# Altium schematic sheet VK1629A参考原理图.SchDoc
size A3
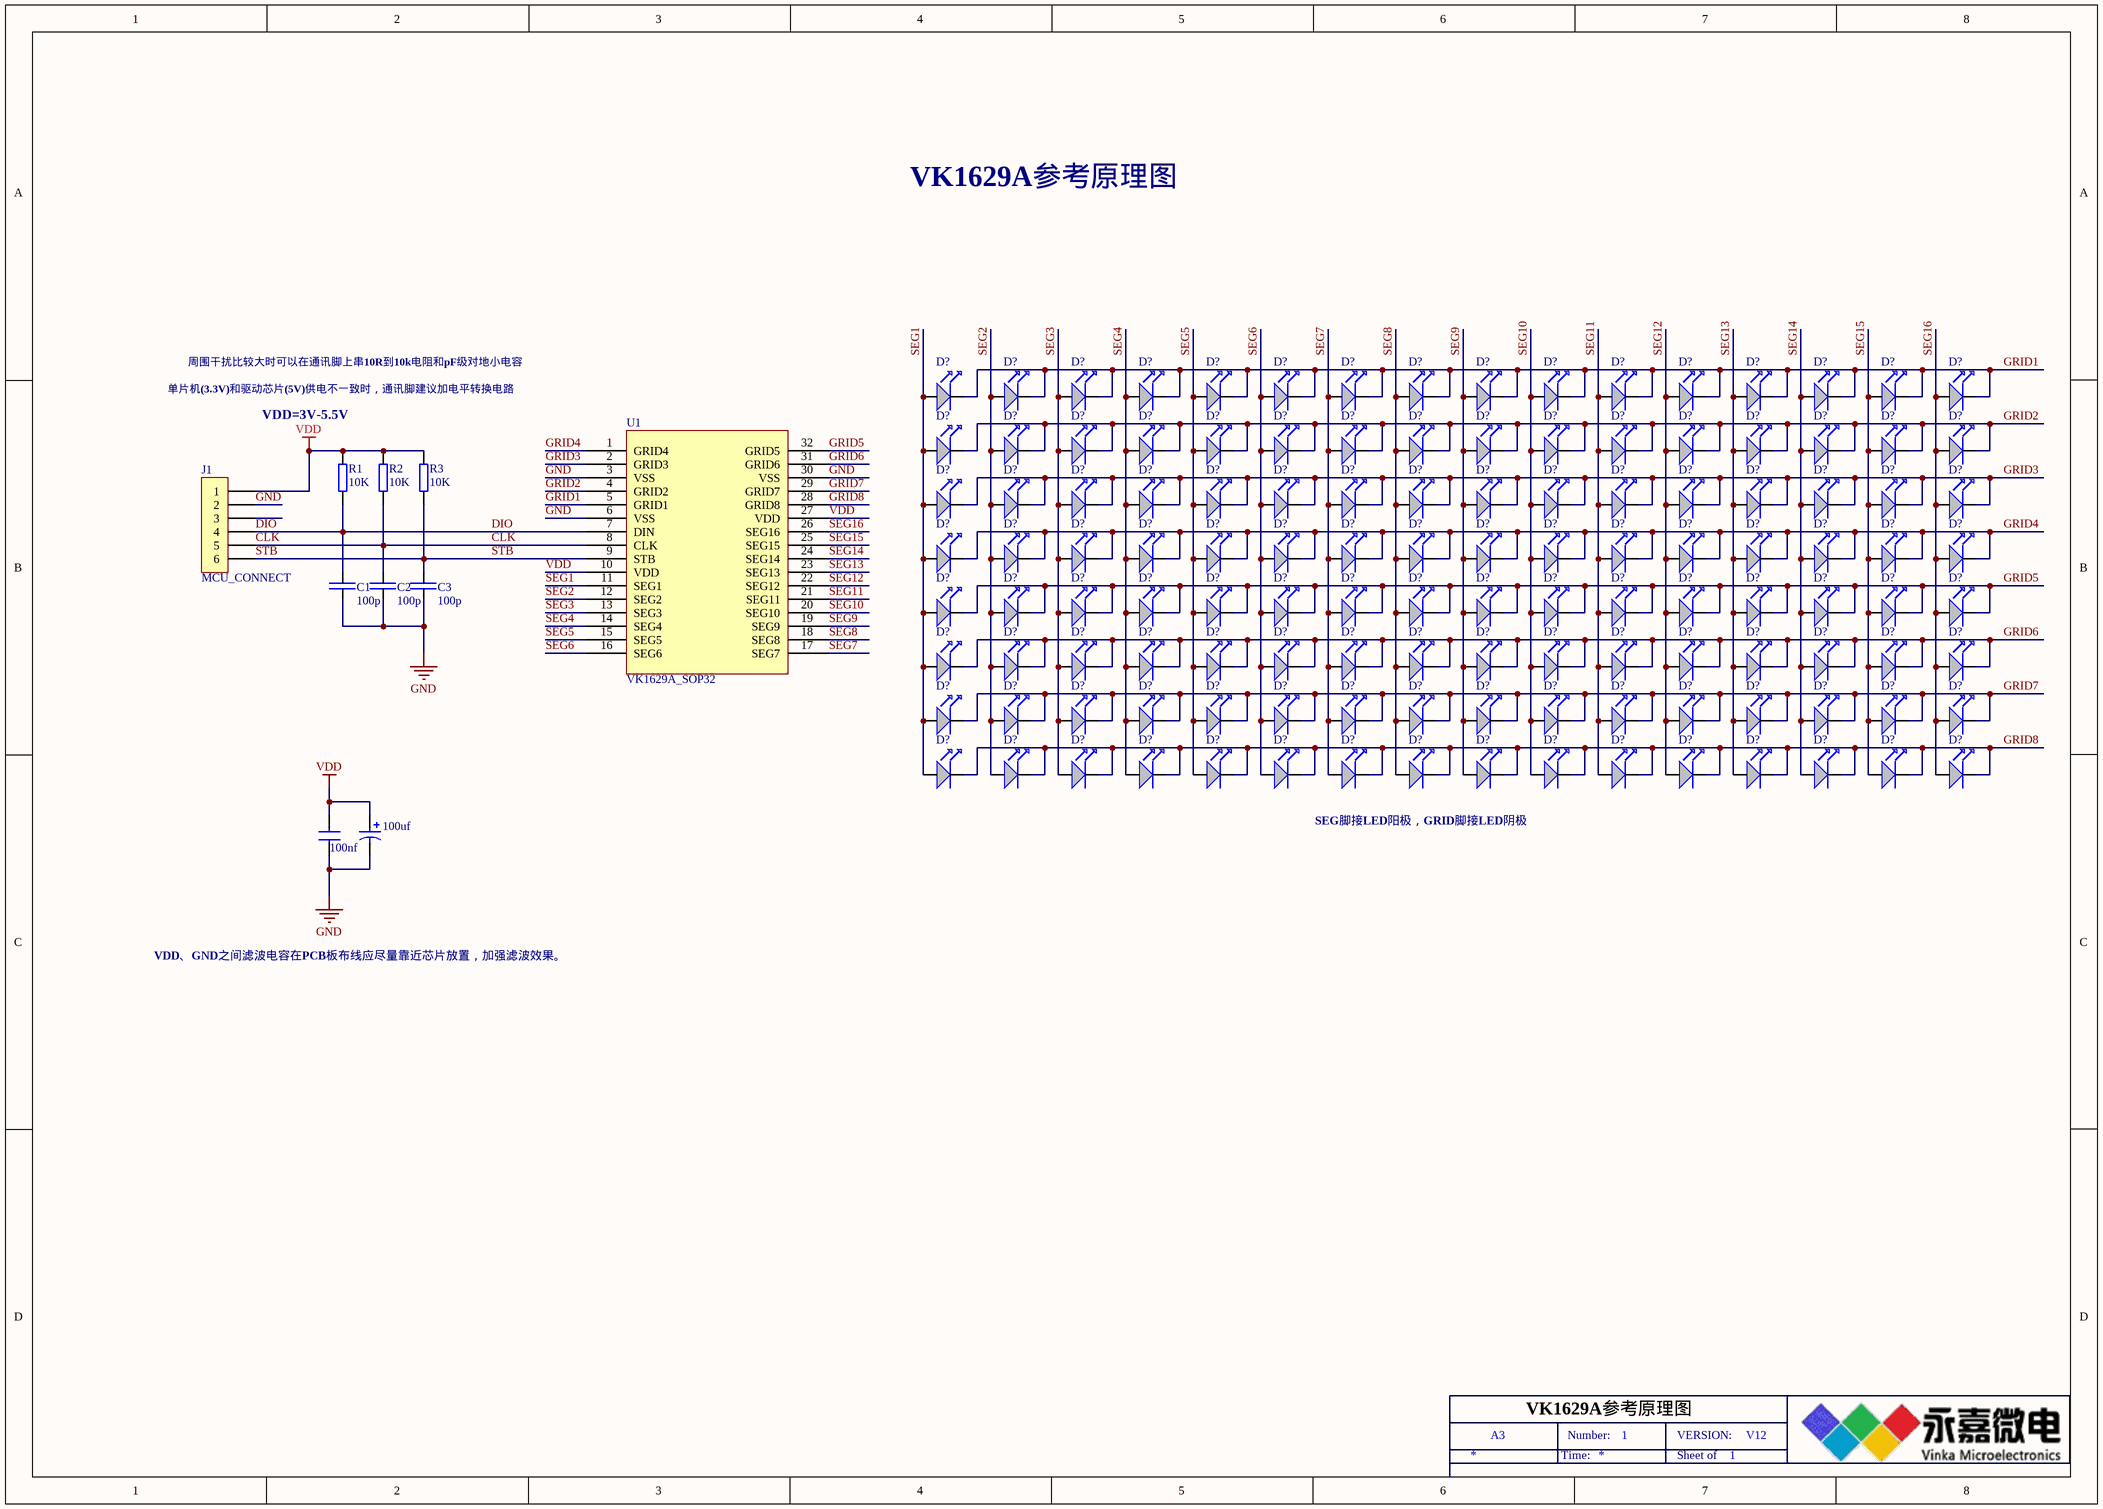
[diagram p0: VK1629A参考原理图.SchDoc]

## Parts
(Parts that share a designator on the sheet are numbered #1, #2 ... from top to bottom, then left to right.)
100nf  CAP  (value not drawn)
100uf  CAP2  (value not drawn)
C1  100p  [C0603]
C2  100p  [C0603]
C3  100p  [C0603]
D?#1  (no value)  [1206-LED]
D?#2  (no value)  [1206-LED]
D?#3  (no value)  [1206-LED]
D?#4  (no value)  [1206-LED]
D?#5  (no value)  [1206-LED]
D?#6  (no value)  [1206-LED]
D?#7  (no value)  [1206-LED]
D?#8  (no value)  [1206-LED]
D?#9  (no value)  [1206-LED]
D?#10  (no value)  [1206-LED]
D?#11  (no value)  [1206-LED]
D?#12  (no value)  [1206-LED]
D?#13  (no value)  [1206-LED]
D?#14  (no value)  [1206-LED]
D?#15  (no value)  [1206-LED]
D?#16  (no value)  [1206-LED]
D?#17  (no value)  [1206-LED]
D?#18  (no value)  [1206-LED]
D?#19  (no value)  [1206-LED]
D?#20  (no value)  [1206-LED]
D?#21  (no value)  [1206-LED]
D?#22  (no value)  [1206-LED]
D?#23  (no value)  [1206-LED]
D?#24  (no value)  [1206-LED]
D?#25  (no value)  [1206-LED]
D?#26  (no value)  [1206-LED]
D?#27  (no value)  [1206-LED]
D?#28  (no value)  [1206-LED]
D?#29  (no value)  [1206-LED]
D?#30  (no value)  [1206-LED]
D?#31  (no value)  [1206-LED]
D?#32  (no value)  [1206-LED]
D?#33  (no value)  [1206-LED]
D?#34  (no value)  [1206-LED]
D?#35  (no value)  [1206-LED]
D?#36  (no value)  [1206-LED]
D?#37  (no value)  [1206-LED]
D?#38  (no value)  [1206-LED]
D?#39  (no value)  [1206-LED]
D?#40  (no value)  [1206-LED]
D?#41  (no value)  [1206-LED]
D?#42  (no value)  [1206-LED]
D?#43  (no value)  [1206-LED]
D?#44  (no value)  [1206-LED]
D?#45  (no value)  [1206-LED]
D?#46  (no value)  [1206-LED]
D?#47  (no value)  [1206-LED]
D?#48  (no value)  [1206-LED]
D?#49  (no value)  [1206-LED]
D?#50  (no value)  [1206-LED]
D?#51  (no value)  [1206-LED]
D?#52  (no value)  [1206-LED]
D?#53  (no value)  [1206-LED]
D?#54  (no value)  [1206-LED]
D?#55  (no value)  [1206-LED]
D?#56  (no value)  [1206-LED]
D?#57  (no value)  [1206-LED]
D?#58  (no value)  [1206-LED]
D?#59  (no value)  [1206-LED]
D?#60  (no value)  [1206-LED]
D?#61  (no value)  [1206-LED]
D?#62  (no value)  [1206-LED]
D?#63  (no value)  [1206-LED]
D?#64  (no value)  [1206-LED]
D?#65  (no value)  [1206-LED]
D?#66  (no value)  [1206-LED]
D?#67  (no value)  [1206-LED]
D?#68  (no value)  [1206-LED]
D?#69  (no value)  [1206-LED]
D?#70  (no value)  [1206-LED]
D?#71  (no value)  [1206-LED]
D?#72  (no value)  [1206-LED]
D?#73  (no value)  [1206-LED]
D?#74  (no value)  [1206-LED]
D?#75  (no value)  [1206-LED]
D?#76  (no value)  [1206-LED]
D?#77  (no value)  [1206-LED]
D?#78  (no value)  [1206-LED]
D?#79  (no value)  [1206-LED]
D?#80  (no value)  [1206-LED]
D?#81  (no value)  [1206-LED]
D?#82  (no value)  [1206-LED]
D?#83  (no value)  [1206-LED]
D?#84  (no value)  [1206-LED]
D?#85  (no value)  [1206-LED]
D?#86  (no value)  [1206-LED]
D?#87  (no value)  [1206-LED]
D?#88  (no value)  [1206-LED]
D?#89  (no value)  [1206-LED]
D?#90  (no value)  [1206-LED]
D?#91  (no value)  [1206-LED]
D?#92  (no value)  [1206-LED]
D?#93  (no value)  [1206-LED]
D?#94  (no value)  [1206-LED]
D?#95  (no value)  [1206-LED]
D?#96  (no value)  [1206-LED]
D?#97  (no value)  [1206-LED]
D?#98  (no value)  [1206-LED]
D?#99  (no value)  [1206-LED]
D?#100  (no value)  [1206-LED]
D?#101  (no value)  [1206-LED]
D?#102  (no value)  [1206-LED]
D?#103  (no value)  [1206-LED]
D?#104  (no value)  [1206-LED]
D?#105  (no value)  [1206-LED]
D?#106  (no value)  [1206-LED]
D?#107  (no value)  [1206-LED]
D?#108  (no value)  [1206-LED]
D?#109  (no value)  [1206-LED]
D?#110  (no value)  [1206-LED]
D?#111  (no value)  [1206-LED]
D?#112  (no value)  [1206-LED]
D?#113  (no value)  [1206-LED]
D?#114  (no value)  [1206-LED]
D?#115  (no value)  [1206-LED]
D?#116  (no value)  [1206-LED]
D?#117  (no value)  [1206-LED]
D?#118  (no value)  [1206-LED]
D?#119  (no value)  [1206-LED]
D?#120  (no value)  [1206-LED]
D?#121  (no value)  [1206-LED]
D?#122  (no value)  [1206-LED]
D?#123  (no value)  [1206-LED]
D?#124  (no value)  [1206-LED]
D?#125  (no value)  [1206-LED]
D?#126  (no value)  [1206-LED]
D?#127  (no value)  [1206-LED]
D?#128  (no value)  [1206-LED]
J1  MCU_CONNECT
R1  10K  [0603-R]
R2  10K  [0603-R]
R3  10K  [0603-R]
U1  VK1629A_SOP32

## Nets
GND: 100nf.2 100uf.2 C1.2 C2.2 C3.2 J1.2 U1.3(VSS) U1.6(VSS) U1.30(VSS)
VDD: 100nf.1 100uf.1 J1.1 R1.1 R2.1 R3.1 U1.10(VDD) U1.27(VDD)
CLK: C2.1 J1.5 R2.2 U1.8(CLK)
DIO: C1.1 J1.4 R1.2 U1.7(DIN)
GRID1: D?#1.2 D?#2.2 D?#3.2 D?#4.2 D?#5.2 D?#6.2 D?#7.2 D?#8.2 D?#9.2 D?#10.2 D?#11.2 D?#12.2 D?#13.2 D?#14.2 D?#15.2 D?#16.2 U1.5(GRID1)
GRID2: D?#17.2 D?#18.2 D?#19.2 D?#20.2 D?#21.2 D?#22.2 D?#23.2 D?#24.2 D?#25.2 D?#26.2 D?#27.2 D?#28.2 D?#29.2 D?#30.2 D?#31.2 D?#32.2 U1.4(GRID2)
GRID3: D?#33.2 D?#34.2 D?#35.2 D?#36.2 D?#37.2 D?#38.2 D?#39.2 D?#40.2 D?#41.2 D?#42.2 D?#43.2 D?#44.2 D?#45.2 D?#46.2 D?#47.2 D?#48.2 U1.2(GRID3)
GRID4: D?#49.2 D?#50.2 D?#51.2 D?#52.2 D?#53.2 D?#54.2 D?#55.2 D?#56.2 D?#57.2 D?#58.2 D?#59.2 D?#60.2 D?#61.2 D?#62.2 D?#63.2 D?#64.2 U1.1(GRID4)
GRID5: D?#65.2 D?#66.2 D?#67.2 D?#68.2 D?#69.2 D?#70.2 D?#71.2 D?#72.2 D?#73.2 D?#74.2 D?#75.2 D?#76.2 D?#77.2 D?#78.2 D?#79.2 D?#80.2 U1.32(GRID5)
GRID6: D?#81.2 D?#82.2 D?#83.2 D?#84.2 D?#85.2 D?#86.2 D?#87.2 D?#88.2 D?#89.2 D?#90.2 D?#91.2 D?#92.2 D?#93.2 D?#94.2 D?#95.2 D?#96.2 U1.31(GRID6)
GRID7: D?#97.2 D?#98.2 D?#99.2 D?#100.2 D?#101.2 D?#102.2 D?#103.2 D?#104.2 D?#105.2 D?#106.2 D?#107.2 D?#108.2 D?#109.2 D?#110.2 D?#111.2 D?#112.2 U1.29(GRID7)
GRID8: D?#113.2 D?#114.2 D?#115.2 D?#116.2 D?#117.2 D?#118.2 D?#119.2 D?#120.2 D?#121.2 D?#122.2 D?#123.2 D?#124.2 D?#125.2 D?#126.2 D?#127.2 D?#128.2 U1.28(GRID8)
SEG1: D?#1.1 D?#17.1 D?#33.1 D?#49.1 D?#65.1 D?#81.1 D?#97.1 D?#113.1 U1.11(SEG1)
SEG2: D?#2.1 D?#18.1 D?#34.1 D?#50.1 D?#66.1 D?#82.1 D?#98.1 D?#114.1 U1.12(SEG2)
SEG3: D?#3.1 D?#19.1 D?#35.1 D?#51.1 D?#67.1 D?#83.1 D?#99.1 D?#115.1 U1.13(SEG3)
SEG4: D?#4.1 D?#20.1 D?#36.1 D?#52.1 D?#68.1 D?#84.1 D?#100.1 D?#116.1 U1.14(SEG4)
SEG5: D?#5.1 D?#21.1 D?#37.1 D?#53.1 D?#69.1 D?#85.1 D?#101.1 D?#117.1 U1.15(SEG5)
SEG6: D?#6.1 D?#22.1 D?#38.1 D?#54.1 D?#70.1 D?#86.1 D?#102.1 D?#118.1 U1.16(SEG6)
SEG7: D?#7.1 D?#23.1 D?#39.1 D?#55.1 D?#71.1 D?#87.1 D?#103.1 D?#119.1 U1.17(SEG7)
SEG8: D?#8.1 D?#24.1 D?#40.1 D?#56.1 D?#72.1 D?#88.1 D?#104.1 D?#120.1 U1.18(SEG8)
SEG9: D?#9.1 D?#25.1 D?#41.1 D?#57.1 D?#73.1 D?#89.1 D?#105.1 D?#121.1 U1.19(SEG9)
SEG10: D?#10.1 D?#26.1 D?#42.1 D?#58.1 D?#74.1 D?#90.1 D?#106.1 D?#122.1 U1.20(SEG10)
SEG11: D?#11.1 D?#27.1 D?#43.1 D?#59.1 D?#75.1 D?#91.1 D?#107.1 D?#123.1 U1.21(SEG11)
SEG12: D?#12.1 D?#28.1 D?#44.1 D?#60.1 D?#76.1 D?#92.1 D?#108.1 D?#124.1 U1.22(SEG12)
SEG13: D?#13.1 D?#29.1 D?#45.1 D?#61.1 D?#77.1 D?#93.1 D?#109.1 D?#125.1 U1.23(SEG13)
SEG14: D?#14.1 D?#30.1 D?#46.1 D?#62.1 D?#78.1 D?#94.1 D?#110.1 D?#126.1 U1.24(SEG14)
SEG15: D?#15.1 D?#31.1 D?#47.1 D?#63.1 D?#79.1 D?#95.1 D?#111.1 D?#127.1 U1.25(SEG15)
SEG16: D?#16.1 D?#32.1 D?#48.1 D?#64.1 D?#80.1 D?#96.1 D?#112.1 D?#128.1 U1.26(SEG16)
STB: C3.1 J1.6 R3.2 U1.9(STB)

Not connected (* = marked no-connect by the designer): J1 3

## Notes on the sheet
- VK1629A参考原理图
- 周围干扰比较大时可以在通讯脚上串10R到10k电阻和pF级对地小电容
- 单片机(3.3V)和驱动芯片(5V)供电不一致时，通讯脚建议加电平转换电路
- VDD=3V-5.5V
- (near D?#119) SEG脚接LED阳极，GRID脚接LED阴极
- VDD、GND之间滤波电容在PCB板布线应尽量靠近芯片放置，加强滤波效果。
- A3
- Time:
- Number:
- 1
- Sheet of
- VERSION:
- V12

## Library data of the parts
100nf = CAP: Capacitor
100uf = CAP2: Bi-Polar Capacitor
C1-C3 = CAP: 分类: 电容; 参数: 20%,50V,X5R
D?#1-D?#128 = LED: Text Field1: 30; Text Field2: 20
J1 = CON6: Connector
R1-R3 = RES: Resistor
U1 = VK1629A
